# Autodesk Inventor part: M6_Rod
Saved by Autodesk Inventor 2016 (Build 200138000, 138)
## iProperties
Created: 2015-11
Part Number: M6_Rod
Material: Generic
Document SubType Name: Modeling
Designer: John
Density: 1 g/cm^3
Appearance: Default
Author: John
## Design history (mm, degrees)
feature "SOLID1"
body "Solid1"
